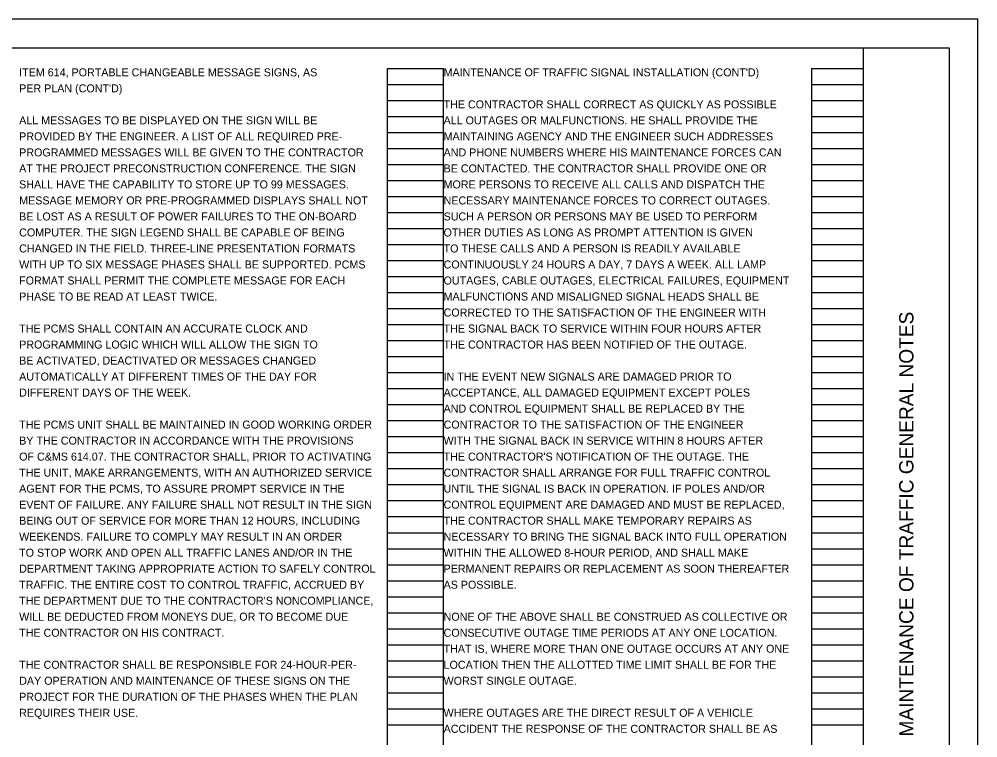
# Model space of a CAD drawing. Extents: x 0 to 34, y 0 to 22.
# Drawn here: x 17.24 to 34, y 9.43 to 22 of the extents above; entities that cross this region are included whole.
import ezdxf

# ---------------------------------------------------------------- set-up
doc = ezdxf.new("R2010")
doc.units = 0
for name, color, linetype in [('SC_Scratch1', 7, 'Continuous'), ('SH_Border', 7, 'Continuous'), ('SH_Cut_Line', 7, 'Continuous'), ('SH_Data', 7, 'Continuous'), ('SH_Text', 7, 'Continuous')]:
    doc.layers.add(name, color=color, linetype=linetype)

msp = doc.modelspace()

# ---------------------------------------------------------------- linework, layer by layer
at = {"layer": 'SC_Scratch1'}
for p, q in [((23.68, 0.98), (23.68, 21.14)), ((23.68, 21.14), (24.66, 21.14)), ((24.66, 0.98), (24.66, 21.14)), ((31.1, 0.98), (31.1, 21.14)), ((31.1, 21.14), (32, 21.14)), ((32, 0.98), (32, 21.14)), ((23.68, 20.86), (24.66, 20.86)), ((31.1, 20.86), (32, 20.86)), ((23.68, 20.58), (24.66, 20.58)), ((31.1, 20.58), (32, 20.58)), ((23.68, 20.3), (24.66, 20.3)), ((31.1, 20.3), (32, 20.3)), ((23.68, 20.02), (24.66, 20.02)), ((31.1, 20.02), (32, 20.02)), ((23.68, 19.74), (24.66, 19.74)), ((31.1, 19.74), (32, 19.74)), ((23.68, 19.46), (24.66, 19.46)), ((31.1, 19.46), (32, 19.46)), ((23.68, 19.18), (24.66, 19.18)), ((31.1, 19.18), (32, 19.18)), ((23.68, 18.9), (24.66, 18.9)), ((31.1, 18.9), (32, 18.9)), ((23.68, 18.62), (24.66, 18.62)), ((31.1, 18.62), (32, 18.62)), ((23.68, 18.34), (24.66, 18.34)), ((31.1, 18.34), (32, 18.34)), ((23.68, 18.06), (24.66, 18.06)), ((31.1, 18.06), (32, 18.06)), ((23.68, 17.78), (24.66, 17.78)), ((31.1, 17.78), (32, 17.78)), ((23.68, 17.5), (24.66, 17.5)), ((31.1, 17.5), (32, 17.5)), ((23.68, 17.22), (24.66, 17.22)), ((31.1, 17.22), (32, 17.22)), ((23.68, 16.94), (24.66, 16.94)), ((31.1, 16.94), (32, 16.94)), ((23.68, 16.66), (24.66, 16.66)), ((31.1, 16.66), (32, 16.66)), ((23.68, 16.38), (24.66, 16.38)), ((31.1, 16.38), (32, 16.38)), ((23.68, 16.1), (24.66, 16.1)), ((31.1, 16.1), (32, 16.1)), ((23.68, 15.82), (24.66, 15.82)), ((31.1, 15.82), (32, 15.82)), ((23.68, 15.54), (24.66, 15.54)), ((31.1, 15.54), (32, 15.54)), ((23.68, 15.26), (24.66, 15.26)), ((31.1, 15.26), (32, 15.26)), ((23.68, 14.98), (24.66, 14.98)), ((31.1, 14.98), (32, 14.98)), ((23.68, 14.7), (24.66, 14.7)), ((31.1, 14.7), (32, 14.7)), ((23.68, 14.42), (24.66, 14.42)), ((31.1, 14.42), (32, 14.42)), ((23.68, 14.14), (24.66, 14.14)), ((31.1, 14.14), (32, 14.14)), ((23.68, 13.86), (24.66, 13.86)), ((31.1, 13.86), (32, 13.86)), ((23.68, 13.58), (24.66, 13.58)), ((31.1, 13.58), (32, 13.58)), ((23.68, 13.3), (24.66, 13.3)), ((31.1, 13.3), (32, 13.3)), ((23.68, 13.02), (24.66, 13.02)), ((31.1, 13.02), (32, 13.02)), ((23.68, 12.74), (24.66, 12.74)), ((31.1, 12.74), (32, 12.74)), ((23.68, 12.46), (24.66, 12.46)), ((31.1, 12.46), (32, 12.46)), ((23.68, 12.18), (24.66, 12.18)), ((31.1, 12.18), (32, 12.18)), ((23.68, 11.9), (24.66, 11.9)), ((31.1, 11.9), (32, 11.9)), ((23.68, 11.62), (24.66, 11.62)), ((31.1, 11.62), (32, 11.62)), ((23.68, 11.34), (24.66, 11.34)), ((31.1, 11.34), (32, 11.34)), ((23.68, 11.06), (24.66, 11.06)), ((31.1, 11.06), (32, 11.06)), ((23.68, 10.78), (24.66, 10.78)), ((31.1, 10.78), (32, 10.78)), ((23.68, 10.5), (24.66, 10.5)), ((31.1, 10.5), (32, 10.5)), ((23.68, 10.22), (24.66, 10.22)), ((31.1, 10.22), (32, 10.22)), ((23.68, 9.94), (24.66, 9.94)), ((31.1, 9.94), (32, 9.94)), ((23.68, 9.66), (24.66, 9.66)), ((31.1, 9.66), (32, 9.66))]:
    msp.add_line(p, q, dxfattribs=at)
at = {"layer": 'SH_Border'}
msp.add_line((32, 0.5), (32, 21.5), dxfattribs=at)
msp.add_lwpolyline([(1.5, 21.5), (33.5, 21.5), (33.5, 0.5), (1.5, 0.5)], close=True, dxfattribs=at)
at = {"layer": 'SH_Cut_Line'}
msp.add_lwpolyline([(0, 0), (34, 0), (34, 22), (0, 22)], close=True, dxfattribs=at)

# ---------------------------------------------------------------- texts
at = {"layer": 'SH_Data'}
msp.add_text('MAINTENANCE OF TRAFFIC GENERAL NOTES', height=0.25, rotation=90, dxfattribs=at).set_placement((32.875, 9.455))
at = {"layer": 'SH_Text'}
for s, p in [('ITEM 614, PORTABLE CHANGEABLE MESSAGE SIGNS, AS', (17.24, 21)), ("MAINTENANCE OF TRAFFIC SIGNAL INSTALLATION (CONT'D)", (24.66, 21)), ("PER PLAN (CONT'D)", (17.24, 20.72)), ('THE CONTRACTOR SHALL CORRECT AS QUICKLY AS POSSIBLE', (24.66, 20.44)), ('ALL MESSAGES TO BE DISPLAYED ON THE SIGN WILL BE', (17.24, 20.16)), ('ALL OUTAGES OR MALFUNCTIONS. HE SHALL PROVIDE THE', (24.66, 20.16)), ('PROVIDED BY THE ENGINEER. A LIST OF ALL REQUIRED PRE-', (17.24, 19.88)), ('MAINTAINING AGENCY AND THE ENGINEER SUCH ADDRESSES', (24.66, 19.88)), ('PROGRAMMED MESSAGES WILL BE GIVEN TO THE CONTRACTOR', (17.24, 19.6)), ('AND PHONE NUMBERS WHERE HIS MAINTENANCE FORCES CAN', (24.66, 19.6)), ('AT THE PROJECT PRECONSTRUCTION CONFERENCE. THE SIGN', (17.24, 19.32)), ('BE CONTACTED. THE CONTRACTOR SHALL PROVIDE ONE OR', (24.66, 19.32)), ('SHALL HAVE THE CAPABILITY TO STORE UP TO 99 MESSAGES.', (17.24, 19.04)), ('MORE PERSONS TO RECEIVE ALL CALLS AND DISPATCH THE', (24.66, 19.04)), ('MESSAGE MEMORY OR PRE-PROGRAMMED DISPLAYS SHALL NOT', (17.24, 18.76)), ('NECESSARY MAINTENANCE FORCES TO CORRECT OUTAGES.', (24.66, 18.76)), ('BE LOST AS A RESULT OF POWER FAILURES TO THE ON-BOARD', (17.24, 18.48)), ('SUCH A PERSON OR PERSONS MAY BE USED TO PERFORM', (24.66, 18.48)), ('COMPUTER. THE SIGN LEGEND SHALL BE CAPABLE OF BEING', (17.24, 18.2)), ('OTHER DUTIES AS LONG AS PROMPT ATTENTION IS GIVEN', (24.66, 18.2)), ('CHANGED IN THE FIELD. THREE-LINE PRESENTATION FORMATS', (17.24, 17.92)), ('TO THESE CALLS AND A PERSON IS READILY AVAILABLE', (24.66, 17.92)), ('WITH UP TO SIX MESSAGE PHASES SHALL BE SUPPORTED. PCMS', (17.24, 17.64)), ('CONTINUOUSLY 24 HOURS A DAY, 7 DAYS A WEEK. ALL LAMP', (24.66, 17.64)), ('FORMAT SHALL PERMIT THE COMPLETE MESSAGE FOR EACH', (17.24, 17.36)), ('OUTAGES, CABLE OUTAGES, ELECTRICAL FAILURES, EQUIPMENT', (24.66, 17.36)), ('PHASE TO BE READ AT LEAST TWICE.', (17.24, 17.08)), ('MALFUNCTIONS AND MISALIGNED SIGNAL HEADS SHALL BE', (24.66, 17.08)), ('CORRECTED TO THE SATISFACTION OF THE ENGINEER WITH', (24.66, 16.8)), ('THE PCMS SHALL CONTAIN AN ACCURATE CLOCK AND', (17.24, 16.52)), ('THE SIGNAL BACK TO SERVICE WITHIN FOUR HOURS AFTER', (24.66, 16.52)), ('PROGRAMMING LOGIC WHICH WILL ALLOW THE SIGN TO', (17.24, 16.24)), ('THE CONTRACTOR HAS BEEN NOTIFIED OF THE OUTAGE.', (24.66, 16.24)), ('BE ACTIVATED, DEACTIVATED OR MESSAGES CHANGED', (17.24, 15.96)), ('AUTOMATICALLY AT DIFFERENT TIMES OF THE DAY FOR', (17.24, 15.68)), ('IN THE EVENT NEW SIGNALS ARE DAMAGED PRIOR TO', (24.66, 15.68)), ('DIFFERENT DAYS OF THE WEEK.', (17.24, 15.4)), ('ACCEPTANCE, ALL DAMAGED EQUIPMENT EXCEPT POLES', (24.66, 15.4)), ('AND CONTROL EQUIPMENT SHALL BE REPLACED BY THE', (24.66, 15.12)), ('THE PCMS UNIT SHALL BE MAINTAINED IN GOOD WORKING ORDER', (17.24, 14.84)), ('CONTRACTOR TO THE SATISFACTION OF THE ENGINEER', (24.66, 14.84)), ('BY THE CONTRACTOR IN ACCORDANCE WITH THE PROVISIONS', (17.24, 14.56)), ('WITH THE SIGNAL BACK IN SERVICE WITHIN 8 HOURS AFTER', (24.66, 14.56)), ('OF C&MS 614.07. THE CONTRACTOR SHALL, PRIOR TO ACTIVATING', (17.24, 14.28)), ("THE CONTRACTOR'S NOTIFICATION OF THE OUTAGE. THE", (24.66, 14.28)), ('THE UNIT, MAKE ARRANGEMENTS, WITH AN AUTHORIZED SERVICE', (17.24, 14)), ('CONTRACTOR SHALL ARRANGE FOR FULL TRAFFIC CONTROL', (24.66, 14)), ('AGENT FOR THE PCMS, TO ASSURE PROMPT SERVICE IN THE', (17.24, 13.72)), ('UNTIL THE SIGNAL IS BACK IN OPERATION. IF POLES AND/OR', (24.66, 13.72)), ('EVENT OF FAILURE. ANY FAILURE SHALL NOT RESULT IN THE SIGN', (17.24, 13.44)), ('CONTROL EQUIPMENT ARE DAMAGED AND MUST BE REPLACED,', (24.66, 13.44)), ('BEING OUT OF SERVICE FOR MORE THAN 12 HOURS, INCLUDING', (17.24, 13.16)), ('THE CONTRACTOR SHALL MAKE TEMPORARY REPAIRS AS', (24.66, 13.16)), ('WEEKENDS. FAILURE TO COMPLY MAY RESULT IN AN ORDER', (17.24, 12.88)), ('NECESSARY TO BRING THE SIGNAL BACK INTO FULL OPERATION', (24.66, 12.88)), ('TO STOP WORK AND OPEN ALL TRAFFIC LANES AND/OR IN THE', (17.24, 12.6)), ('WITHIN THE ALLOWED 8-HOUR PERIOD, AND SHALL MAKE', (24.66, 12.6)), ('DEPARTMENT TAKING APPROPRIATE ACTION TO SAFELY CONTROL', (17.24, 12.32)), ('PERMANENT REPAIRS OR REPLACEMENT AS SOON THEREAFTER', (24.66, 12.32)), ('TRAFFIC. THE ENTIRE COST TO CONTROL TRAFFIC, ACCRUED BY', (17.24, 12.04)), ('AS POSSIBLE.', (24.66, 12.04)), ("THE DEPARTMENT DUE TO THE CONTRACTOR'S NONCOMPLIANCE,", (17.24, 11.76)), ('WILL BE DEDUCTED FROM MONEYS DUE, OR TO BECOME DUE', (17.24, 11.48)), ('NONE OF THE ABOVE SHALL BE CONSTRUED AS COLLECTIVE OR', (24.66, 11.48)), ('THE CONTRACTOR ON HIS CONTRACT.', (17.24, 11.2)), ('CONSECUTIVE OUTAGE TIME PERIODS AT ANY ONE LOCATION.', (24.66, 11.2)), ('THAT IS, WHERE MORE THAN ONE OUTAGE OCCURS AT ANY ONE', (24.66, 10.92)), ('THE CONTRACTOR SHALL BE RESPONSIBLE FOR 24-HOUR-PER-', (17.24, 10.64)), ('LOCATION THEN THE ALLOTTED TIME LIMIT SHALL BE FOR THE', (24.66, 10.64)), ('DAY OPERATION AND MAINTENANCE OF THESE SIGNS ON THE', (17.24, 10.36)), ('WORST SINGLE OUTAGE.', (24.66, 10.36)), ('PROJECT FOR THE DURATION OF THE PHASES WHEN THE PLAN', (17.24, 10.08)), ('REQUIRES THEIR USE.', (17.24, 9.8)), ('WHERE OUTAGES ARE THE DIRECT RESULT OF A VEHICLE', (24.66, 9.8)), ('ACCIDENT THE RESPONSE OF THE CONTRACTOR SHALL BE AS', (24.66, 9.52))]:
    msp.add_text(s, height=0.14, dxfattribs=at).set_placement(p)

doc.saveas('drawing.dxf')
